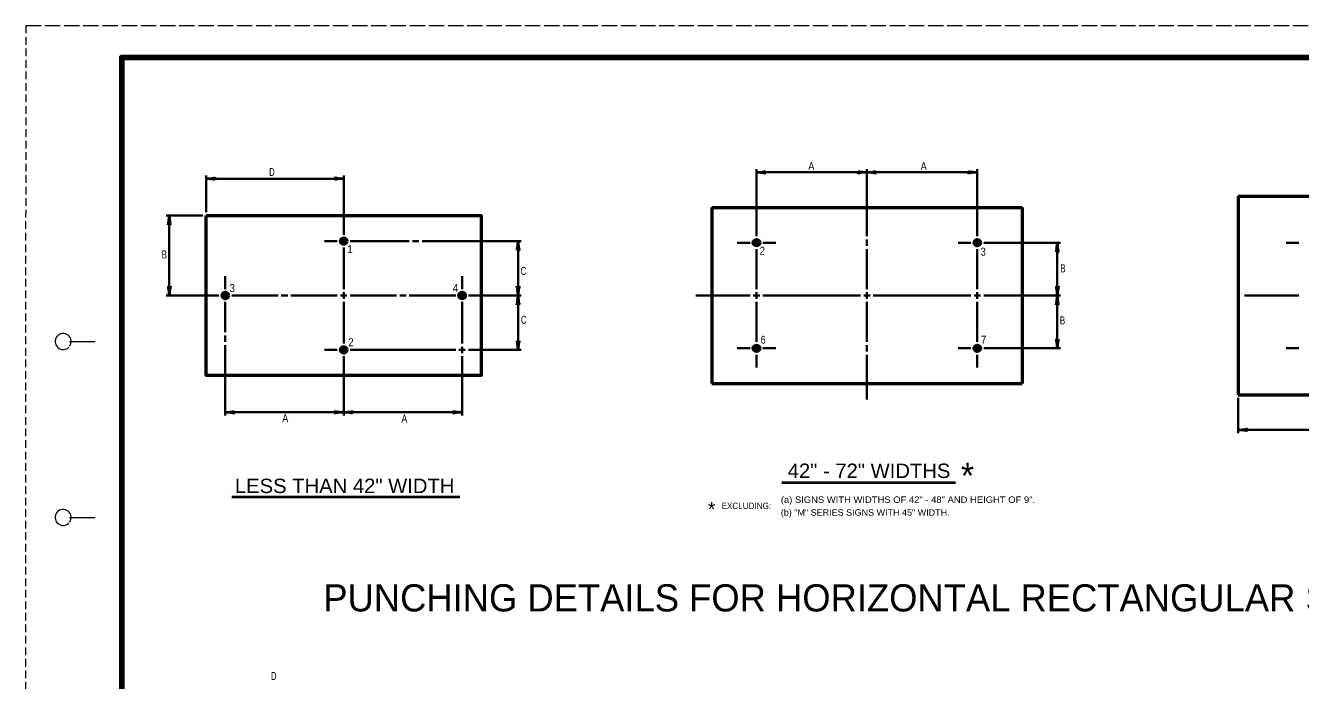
# Model space of a CAD drawing. Extents: x -66 to 614, y -390 to 50.
# Drawn here: x -66 to 332.4, y -154.7 to 50.1 of the extents above; entities that cross this region are included whole.
import ezdxf
from ezdxf.enums import TextEntityAlignment as Align

# ---------------------------------------------------------------- set-up
doc = ezdxf.new("R2010")
doc.units = 0
doc.header["$LTSCALE"] = 0.8
doc.linetypes.add('LONG_DASHED', pattern=[7.5, 6, -1.5])
doc.linetypes.add('MEDIUM_DASHED', pattern=[4.5, 3, -1.5])
doc.layers.add('1', color=7, linetype='Continuous', lineweight=35)
doc.layers.add('61', color=7, linetype='Continuous', lineweight=35)

msp = doc.modelspace()

# ---------------------------------------------------------------- linework, layer by layer
at = {"layer": '1', "linetype": 'MEDIUM_DASHED', "lineweight": 13}
msp.add_line((-65.9312, 50.0569), (-65.9912, -389.9831), dxfattribs=at)
at = {"layer": '1'}
for p, q in [((162.4405, -15.8304), (162.4405, 5.1696)), ((196.9405, 5.1696), (196.9405, -15.8304)), ((231.4405, -15.8304), (231.4405, 5.1696)), ((-9.5595, -8.3304), (-9.5595, 3.1696)), ((-9.5595, 2.1696), (33.4405, 2.1696)), ((33.4405, 3.1696), (33.4405, -15.3304)), ((-10.5595, -9.3304), (-22.0595, -9.3304)), ((-21.0595, -9.3304), (-21.0595, -34.3304)), ((31.4405, -17.3304), (27.4405, -17.3304)), ((32.9405, -17.3304), (33.9405, -17.3304)), ((33.4405, -16.8304), (33.4405, -17.8304)), ((33.4405, -19.3304), (33.4405, -32.3304)), ((35.4405, -17.3304), (53.9405, -17.3304)), ((54.9405, -17.3304), (56.9405, -17.3304)), ((57.9405, -17.3304), (76.4405, -17.3304)), ((76.4405, -17.3304), (88.9405, -17.3304)), ((160.4405, -17.8304), (156.4405, -17.8304)), ((162.9405, -17.8304), (161.9405, -17.8304)), ((162.4405, -18.3304), (162.4405, -17.3304)), ((162.4405, -19.8304), (162.4405, -32.3304)), ((168.4405, -17.8304), (164.4405, -17.8304)), ((196.9405, -16.8304), (196.9405, -18.8304)), ((196.9405, -19.8304), (196.9405, -32.3304)), ((225.4405, -17.8304), (229.4405, -17.8304)), ((230.9405, -17.8304), (231.9405, -17.8304)), ((231.4405, -18.3304), (231.4405, -17.3304)), ((231.4405, -19.8304), (231.4405, -32.3304)), ((233.4405, -17.8304), (257.4405, -17.8304)), ((331.9405, -17.8304), (327.9405, -17.8304)), ((-3.5595, -28.3304), (-3.5595, -32.3304)), ((70.4405, -28.3304), (70.4405, -32.3304)), ((-22.0595, -34.3304), (-5.5595, -34.3304)), ((-4.0595, -34.3304), (-3.0595, -34.3304)), ((-3.5595, -33.8304), (-3.5595, -34.8304)), ((-1.5595, -34.3304), (12.9405, -34.3304)), ((13.9405, -34.3304), (15.9405, -34.3304)), ((16.9405, -34.3304), (31.4405, -34.3304)), ((32.4405, -34.3304), (34.4405, -34.3304)), ((33.4405, -33.3304), (33.4405, -35.3304)), ((35.4405, -34.3304), (49.9405, -34.3304)), ((50.9405, -34.3304), (52.9405, -34.3304)), ((53.9405, -34.3304), (68.4405, -34.3304)), ((69.9405, -34.3304), (70.9405, -34.3304)), ((70.4405, -33.8304), (70.4405, -34.8304)), ((72.4405, -34.3304), (88.9405, -34.3304)), ((143.4405, -34.3304), (160.4405, -34.3304)), ((161.4405, -34.3304), (163.4405, -34.3304)), ((162.4405, -33.3304), (162.4405, -35.3304)), ((164.4405, -34.3304), (194.9405, -34.3304)), ((195.9405, -34.3304), (197.9405, -34.3304)), ((196.9405, -33.3304), (196.9405, -35.3304)), ((198.9405, -34.3304), (229.4405, -34.3304)), ((230.4405, -34.3304), (232.4405, -34.3304)), ((231.4405, -33.3304), (231.4405, -35.3304)), ((233.4405, -34.3304), (257.4405, -34.3304)), ((314.9405, -34.3304), (331.9405, -34.3304)), ((-3.5595, -36.3304), (-3.5595, -45.8304)), ((33.4405, -36.3304), (33.4405, -49.3304)), ((70.4405, -36.3304), (70.4405, -49.3304)), ((162.4405, -48.8304), (162.4405, -36.3304)), ((196.9405, -36.3304), (196.9405, -48.8304)), ((231.4405, -48.8304), (231.4405, -36.3304)), ((-3.5595, -46.8304), (-3.5595, -48.8304)), ((-3.5595, -49.8304), (-3.5595, -59.3304)), ((27.4405, -51.3304), (31.4405, -51.3304)), ((32.9405, -51.3304), (33.9405, -51.3304)), ((33.4405, -50.8304), (33.4405, -51.8304)), ((35.4405, -51.3304), (68.4405, -51.3304)), ((69.4405, -51.3304), (71.4405, -51.3304)), ((70.4405, -50.3304), (70.4405, -52.3304)), ((72.4405, -51.3304), (88.9405, -51.3304)), ((160.4405, -50.8304), (156.4405, -50.8304)), ((162.9405, -50.8304), (161.9405, -50.8304)), ((162.9405, -50.8304), (161.9405, -50.8304)), ((162.4405, -50.3304), (162.4405, -51.3304)), ((162.4405, -50.3304), (162.4405, -51.3304)), ((168.4405, -50.8304), (164.4405, -50.8304)), ((196.9405, -49.8304), (196.9405, -51.8304)), ((225.4405, -50.8304), (229.4405, -50.8304)), ((230.9405, -50.8304), (231.9405, -50.8304)), ((230.9405, -50.8304), (231.9405, -50.8304)), ((231.4405, -50.3304), (231.4405, -51.3304)), ((231.4405, -50.3304), (231.4405, -51.3304)), ((233.4405, -50.8304), (257.4405, -50.8304)), ((331.9405, -50.8304), (327.9405, -50.8304)), ((33.4405, -53.3304), (33.4405, -71.8304)), ((70.4405, -53.3304), (70.4405, -71.8304)), ((162.4405, -52.8304), (162.4405, -56.8304)), ((196.9405, -52.8304), (196.9405, -66.8304)), ((231.4405, -52.8304), (231.4405, -56.8304)), ((-3.5595, -59.3304), (-3.5595, -71.8304)), ((312.9405, -66.3304), (312.9405, -77.3304)), ((312.9405, -76.3304), (368.4405, -76.3304))]:
    msp.add_line(p, q, dxfattribs=at)
at = {"layer": '1', "lineweight": 53}
for p, q in [((312.9405, -3.3304), (312.9405, -65.3304)), ((312.9405, -3.3304), (423.9405, -3.3304)), ((148.4405, -6.8304), (148.4405, -61.8304)), ((148.4405, -6.8304), (245.4405, -6.8304)), ((245.4405, -6.8304), (245.4405, -61.8304)), ((148.4405, -61.8304), (245.4405, -61.8304)), ((312.9405, -65.3304), (423.9405, -65.3304))]:
    msp.add_line(p, q, dxfattribs=at)
at = {"layer": '1', "lineweight": 40}
for p, q in [((170.3457, -92.8132), (224.6536, -92.8132)), ((-1.4883, -97.301), (69.714, -97.301))]:
    msp.add_line(p, q, dxfattribs=at)
at = {"layer": '1'}
for points in [[(162.4405, 4.1696), (196.9405, 4.1696), (231.4405, 4.1696)], [(87.9405, -51.3304), (87.9405, -34.3304), (87.9405, -17.3304)], [(256.4405, -17.8304), (256.4405, -34.3304), (256.4405, -50.8304)], [(-3.5595, -70.8304), (33.4405, -70.8304), (70.4405, -70.8304)]]:
    msp.add_lwpolyline(points, dxfattribs=at)
at = {"layer": '1', "lineweight": 53}
msp.add_lwpolyline([(-9.5595, -9.3304), (76.4405, -9.3304), (76.4405, -59.3304), (-9.5595, -59.3304)], close=True, dxfattribs=at)
for centre in [(33.4405, -17.3304), (162.4405, -17.8304), (231.4405, -17.8304), (-3.5595, -34.3304), (70.4405, -34.3304), (33.4405, -51.3304), (162.4405, -50.8304), (231.4405, -50.8304)]:
    msp.add_circle(centre, 1, dxfattribs=at)
at = {"layer": '1', "lineweight": 40}
for centre, major_axis, ratio, start_param, end_param in [((163.561, 3.958), (-1.7565, 0.1757), 0.07063, 3.14071475, 5.41810995), ((163.561, 3.958), (-1.7565, 0.1757), 0.07063, 3.14071475, 5.41810995), ((163.5317, 4.4459), (-1.7857, -0.1562), 0.122415, 0.89635335, 3.14159265), ((163.5317, 4.4459), (-1.7857, -0.1562), 0.122415, 0.89635335, 3.14159265), ((195.8493, 3.8933), (1.7857, 0.1562), 0.122415, 0.89635335, 3.14159265), ((195.8493, 3.8933), (1.7857, 0.1562), 0.122415, 0.89635335, 3.14159265), ((195.82, 4.3812), (1.7565, -0.1757), 0.07063, 3.14071475, 5.41810995), ((195.82, 4.3812), (1.7565, -0.1757), 0.07063, 3.14071475, 5.41810995), ((198.061, 3.958), (-1.7565, 0.1757), 0.07063, 3.14071475, 5.41810995), ((198.061, 3.958), (-1.7565, 0.1757), 0.07063, 3.14071475, 5.41810995), ((198.0317, 4.4459), (-1.7857, -0.1562), 0.122415, 0.89635335, 3.14159265), ((198.0317, 4.4459), (-1.7857, -0.1562), 0.122415, 0.89635335, 3.14159265), ((230.3493, 3.8933), (1.7857, 0.1562), 0.122415, 0.89635335, 3.14159265), ((230.3493, 3.8933), (1.7857, 0.1562), 0.122415, 0.89635335, 3.14159265), ((230.32, 4.3812), (1.7565, -0.1757), 0.07063, 3.14071475, 5.41810995), ((230.32, 4.3812), (1.7565, -0.1757), 0.07063, 3.14071475, 5.41810995), ((-8.439, 1.958), (-1.7565, 0.1757), 0.07063, 3.14071475, 5.41810995), ((-8.439, 1.958), (-1.7565, 0.1757), 0.07063, 3.14071475, 5.41810995), ((-8.4683, 2.4459), (-1.7857, -0.1562), 0.122415, 0.89635335, 3.14159265), ((-8.4683, 2.4459), (-1.7857, -0.1562), 0.122415, 0.89635335, 3.14159265), ((32.3493, 1.8933), (1.7857, 0.1562), 0.122415, 0.89635335, 3.14159265), ((32.3493, 1.8933), (1.7857, 0.1562), 0.122415, 0.89635335, 3.14159265), ((32.32, 2.3812), (1.7565, -0.1757), 0.07063, 3.14071475, 5.41810995), ((32.32, 2.3812), (1.7565, -0.1757), 0.07063, 3.14071475, 5.41810995), ((-21.2711, -10.4509), (0.1757, 1.7565), 0.07063, 3.14071475, 5.41810995), ((-21.2711, -10.4509), (0.1757, 1.7565), 0.07063, 3.14071475, 5.41810995), ((-20.7832, -10.4216), (-0.1562, 1.7857), 0.122415, 0.89635335, 3.14159265), ((-20.7832, -10.4216), (-0.1562, 1.7857), 0.122415, 0.89635335, 3.14159265), ((87.7289, -18.4509), (0.1757, 1.7565), 0.07063, 3.14071475, 5.41810995), ((87.7289, -18.4509), (0.1757, 1.7565), 0.07063, 3.14071475, 5.41810995), ((88.2168, -18.4216), (-0.1562, 1.7857), 0.122415, 0.89635335, 3.14159265), ((88.2168, -18.4216), (-0.1562, 1.7857), 0.122415, 0.89635335, 3.14159265), ((256.2289, -18.9509), (0.1757, 1.7565), 0.07063, 3.14071475, 5.41810995), ((256.7168, -18.9216), (-0.1562, 1.7857), 0.122415, 0.89635335, 3.14159265), ((-21.3358, -33.2392), (0.1562, -1.7857), 0.122415, 0.89635335, 3.14159265), ((-21.3358, -33.2392), (0.1562, -1.7857), 0.122415, 0.89635335, 3.14159265), ((-20.8479, -33.2099), (-0.1757, -1.7565), 0.07063, 3.14071475, 5.41810995), ((-20.8479, -33.2099), (-0.1757, -1.7565), 0.07063, 3.14071475, 5.41810995), ((87.6642, -33.2392), (0.1562, -1.7857), 0.122415, 0.89635335, 3.14159265), ((88.1521, -33.2099), (-0.1757, -1.7565), 0.07063, 3.14071475, 5.41810995), ((256.1642, -33.2392), (0.1562, -1.7857), 0.122415, 0.89635335, 3.14159265), ((256.1642, -33.2392), (0.1562, -1.7857), 0.122415, 0.89635335, 3.14159265), ((256.6521, -33.2099), (-0.1757, -1.7565), 0.07063, 3.14071475, 5.41810995), ((256.6521, -33.2099), (-0.1757, -1.7565), 0.07063, 3.14071475, 5.41810995), ((87.7289, -35.4509), (0.1757, 1.7565), 0.07063, 3.14071475, 5.41810995), ((88.2168, -35.4216), (-0.1562, 1.7857), 0.122415, 0.89635335, 3.14159265), ((256.2289, -35.4509), (0.1757, 1.7565), 0.07063, 3.14071475, 5.41810995), ((256.7168, -35.4216), (-0.1562, 1.7857), 0.122415, 0.89635335, 3.14159265), ((87.6642, -50.2392), (0.1562, -1.7857), 0.122415, 0.89635335, 3.14159265), ((87.6642, -50.2392), (0.1562, -1.7857), 0.122415, 0.89635335, 3.14159265), ((88.1521, -50.2099), (-0.1757, -1.7565), 0.07063, 3.14071475, 5.41810995), ((88.1521, -50.2099), (-0.1757, -1.7565), 0.07063, 3.14071475, 5.41810995), ((256.1642, -49.7392), (0.1562, -1.7857), 0.122415, 0.89635335, 3.14159265), ((256.6521, -49.7099), (-0.1757, -1.7565), 0.07063, 3.14071475, 5.41810995), ((-2.439, -71.042), (-1.7565, 0.1757), 0.07063, 3.14071475, 5.41810995), ((-2.439, -71.042), (-1.7565, 0.1757), 0.07063, 3.14071475, 5.41810995), ((-2.439, -71.042), (-1.7565, 0.1757), 0.07063, 3.14071475, 5.41810995), ((-2.4683, -70.5541), (-1.7857, -0.1562), 0.122415, 0.89635335, 3.14159265), ((-2.4683, -70.5541), (-1.7857, -0.1562), 0.122415, 0.89635335, 3.14159265), ((-2.4683, -70.5541), (-1.7857, -0.1562), 0.122415, 0.89635335, 3.14159265), ((32.3493, -71.1067), (1.7857, 0.1562), 0.122415, 0.89635335, 3.14159265), ((32.3493, -71.1067), (1.7857, 0.1562), 0.122415, 0.89635335, 3.14159265), ((32.32, -70.6188), (1.7565, -0.1757), 0.07063, 3.14071475, 5.41810995), ((32.32, -70.6188), (1.7565, -0.1757), 0.07063, 3.14071475, 5.41810995), ((34.561, -71.042), (-1.7565, 0.1757), 0.07063, 3.14071475, 5.41810995), ((34.561, -71.042), (-1.7565, 0.1757), 0.07063, 3.14071475, 5.41810995), ((34.5317, -70.5541), (-1.7857, -0.1562), 0.122415, 0.89635335, 3.14159265), ((34.5317, -70.5541), (-1.7857, -0.1562), 0.122415, 0.89635335, 3.14159265), ((69.3493, -71.1067), (1.7857, 0.1562), 0.122415, 0.89635335, 3.14159265), ((69.32, -70.6188), (1.7565, -0.1757), 0.07063, 3.14071475, 5.41810995), ((314.061, -76.542), (-1.7565, 0.1757), 0.07063, 3.14071475, 5.41810995), ((314.0317, -76.0541), (-1.7857, -0.1562), 0.122415, 0.89635335, 3.14159265)]:
    msp.add_ellipse(centre, major_axis=major_axis, ratio=ratio, start_param=start_param, end_param=end_param, dxfattribs=at)
at = {"layer": '61', "linetype": 'LONG_DASHED', "lineweight": 13}
msp.add_line((-65.9312, 50.0569), (614.0888, 50.0569), dxfattribs=at)
at = {"layer": '61', "lineweight": 13}
for p, q in [((-52.2112, -48.7031), (-44.2312, -48.6831)), ((-52.2312, -103.7031), (-44.2312, -103.7031))]:
    msp.add_line(p, q, dxfattribs=at)
at = {"layer": '61', "lineweight": 158}
msp.add_lwpolyline([(603.1088, 40.0569), (-35.9312, 40.0569), (-35.9312, -379.9631)], dxfattribs=at)
at = {"layer": '61', "lineweight": 13}
for centre, end in [((-54.2334, -48.7018), 316.23216), ((-54.2334, -103.7018), 315.37577)]:
    msp.add_arc(centre, 2.5, 323.13009, end, dxfattribs=at)

# ---------------------------------------------------------------- texts
at = {"layer": '1'}
for s, height, width, p in [('D', 2.5, 0.7, (11.0125, 3.0067)), ('A', 2.5, 0.85, (179.576, 4.8629)), ('A', 2.5, 0.85, (214.6947, 4.8629)), ('2', 2.5, 0.9, (164.2445, -21.6157)), ('3', 2.5, 0.9, (233.3024, -21.8778)), ('B', 2.5, 0.75, (-22.6206, -22.7632)), ('C', 2.5, 0.75, (89.6091, -27.8933)), ('B', 2.5, 0.75, (258.2, -27.1211)), ('3', 2.5, 0.9, (-1.3912, -33.2621)), ('4', 2.5, 0.95, (68.3796, -33.2621)), ('C', 2.5, 0.75, (89.7284, -43.1644)), ('B', 2.5, 0.75, (258.0689, -43.3753)), ('2', 2.5, 0.9, (35.7007, -50.2034)), ('6', 2.5, 0.8, (164.5065, -49.4051)), ('7', 2.5, 0.9, (233.4335, -49.4051)), ('A', 2.5, 0.85, (15.1868, -73.9452)), ('A', 2.5, 0.85, (52.398, -74.0645)), ('42" - 72" WIDTHS', 4.5, 1.05, (197.6135, -91.3716)), ('LESS THAN 42" WIDTH', 4.5, 1.05, (33.7403, -96.0889)), ('EXCLUDING:', 2, 0.95, (159.2732, -101.0643)), ('D', 2.5, 0.7, (11.616, -154.5005))]:
    msp.add_text(s, height=height, dxfattribs=dict(at, width=width)).set_placement(p, align=Align.CENTER)
for s, height, p in [('1', 2.5, (35.389, -21.0929)), ('*', 8, (228.3824, -94.6099)), ('*', 4.5, (148.4149, -103.3672)), ('PUNCHING DETAILS FOR HORIZONTAL RECTANGULAR SIGNS', 8.5, (198.2213, -133.0868))]:
    msp.add_text(s, height=height, dxfattribs=at).set_placement(p, align=Align.CENTER)
for s, width, p in [('(a) SIGNS WITH WIDTHS OF 42" - 48" AND HEIGHT OF 9".', 1.1, (170.0389, -99.1437)), ('(b) "M" SERIES SIGNS WITH 45" WIDTH.', 1.05, (170.0389, -103.1437))]:
    msp.add_text(s, height=2, dxfattribs=dict(at, width=width)).set_placement(p)

doc.saveas('drawing.dxf')
